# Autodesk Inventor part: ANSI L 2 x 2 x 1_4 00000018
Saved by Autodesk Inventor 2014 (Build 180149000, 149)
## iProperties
_FrameMemberDoc: Frame Member File
_Version: 12.0.0
_CCFamilyMember: 11
_CCFamilyDisplayName: ANSI L (Equal angles) - Angle Steel
Created: 2007-02
Part Number: ANSI L 2 x 2 x 1_4 00000018
Material: Steel, Mild
Document SubType Name: Modeling
Standard: ANSI
Designer: hendert
Size Designation: L 2 x 2 x 1/4
Stock Number: L 2 x 2 x 1/4
Density: 1 g/cm^3
Appearance: Steel
G_L: 30.754 in
G_W: 2.000 in
G_H: 2.000 in
+F3A1AB18-BE95-447E-B421-3B8CFA11E5BC+CUTDETAIL1: Cut
+2BFA6F41-8630-48FD-BBC1-F7B563622B76+CUTDETAIL2: Cut
Author: hendert
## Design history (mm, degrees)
node "Start plane"
node "End plane"
sketch "Sketch"
  geometry: L1 (50.8, 0)-(0, 0); L2 (0, 0)-(0, 50.8); L3 (0, 50.8)-(3.302, 50.8); L4 (6.35, 47.752)-(6.35, 12.7); L5 (12.7, 6.35)-(47.752, 6.35); L6 (50.8, 3.302)-(50.8, 0); L7 (0, -11.041)-(0, 31.538); L8 (-11.041, 0)-(31.538, 0); L9 (0, 63.926)-(0, -23.536) reference; L10 (-23.536, 0)-(63.926, 0) reference; A1 r 6.35 centre (12.7, 12.7) between (6.35, 12.7) and (12.7, 6.35); A2 r 3.048 centre (3.302, 47.752) between (6.35, 47.752) and (3.302, 50.8); A3 r 3.048 centre (47.752, 3.302) between (50.8, 3.302) and (47.752, 6.35); 3 further points
  constraints: 16 end point, 6 point on circle, 6 point on line, 6 tangent, 4 parallel, 3 centre point, 2 collinear, 1 equal radius, 1 horizontal, 1 perpendicular
  dimensions: "d0" = 50.8 distance between parallel lines of L6 L2 (= G_H); "d1" = 50.8 distance between parallel lines of L3 L1 (= G_H); "d2" = 6.35 distance between parallel lines of L2 L4 (= G_T); "d3" = 6.35 distance between parallel lines of L1 L5 (= G_T); "d10" = 0 distance between parallel lines of L7 L2 (computed from ex); "d11" = 0 distance between parallel lines of L8 L1 (computed from d10); "d14" = 6.35 radius of A1 (= G_IR); "d15" = 3.048 radius of A2 (= G_ER)
extrude "Body" new body sketch "Sketch" stored distance "d4" = 781.15556 (= G_L); taper "d5" = 0 deg
workplane "Work Plane3"
split "Split1"
workplane "Work Plane4"
split "Split2"
body "Solid1"
other parameters: "G_H" = 50.8 [user parameter; used in 2 equation terms], "G_T" = 6.35 [user parameter; used in 2 equation terms], "G_ER" = 3.048 [user parameter; used in 1 equation term], "G_IR" = 6.35 [user parameter; used in 1 equation term], "G_L" = 781.15556 (= B_L + G_OFFSET_START + G_OFFSET_END) [user parameter; used in 1 equation term], "ex" = 0 [user parameter; used in 1 equation term], "G_OFFSET_START" = -14.68216 [user parameter; used in 2 equation terms], "G_OFFSET_END" = 5.47199 [user parameter; used in 2 equation terms], "d12" = 14.68216 (= -G_OFFSET_START), "d13" = 795.83771 (= G_OFFSET_END + B_L), "B_L" = 790.36573 [user parameter; used in 2 equation terms]
